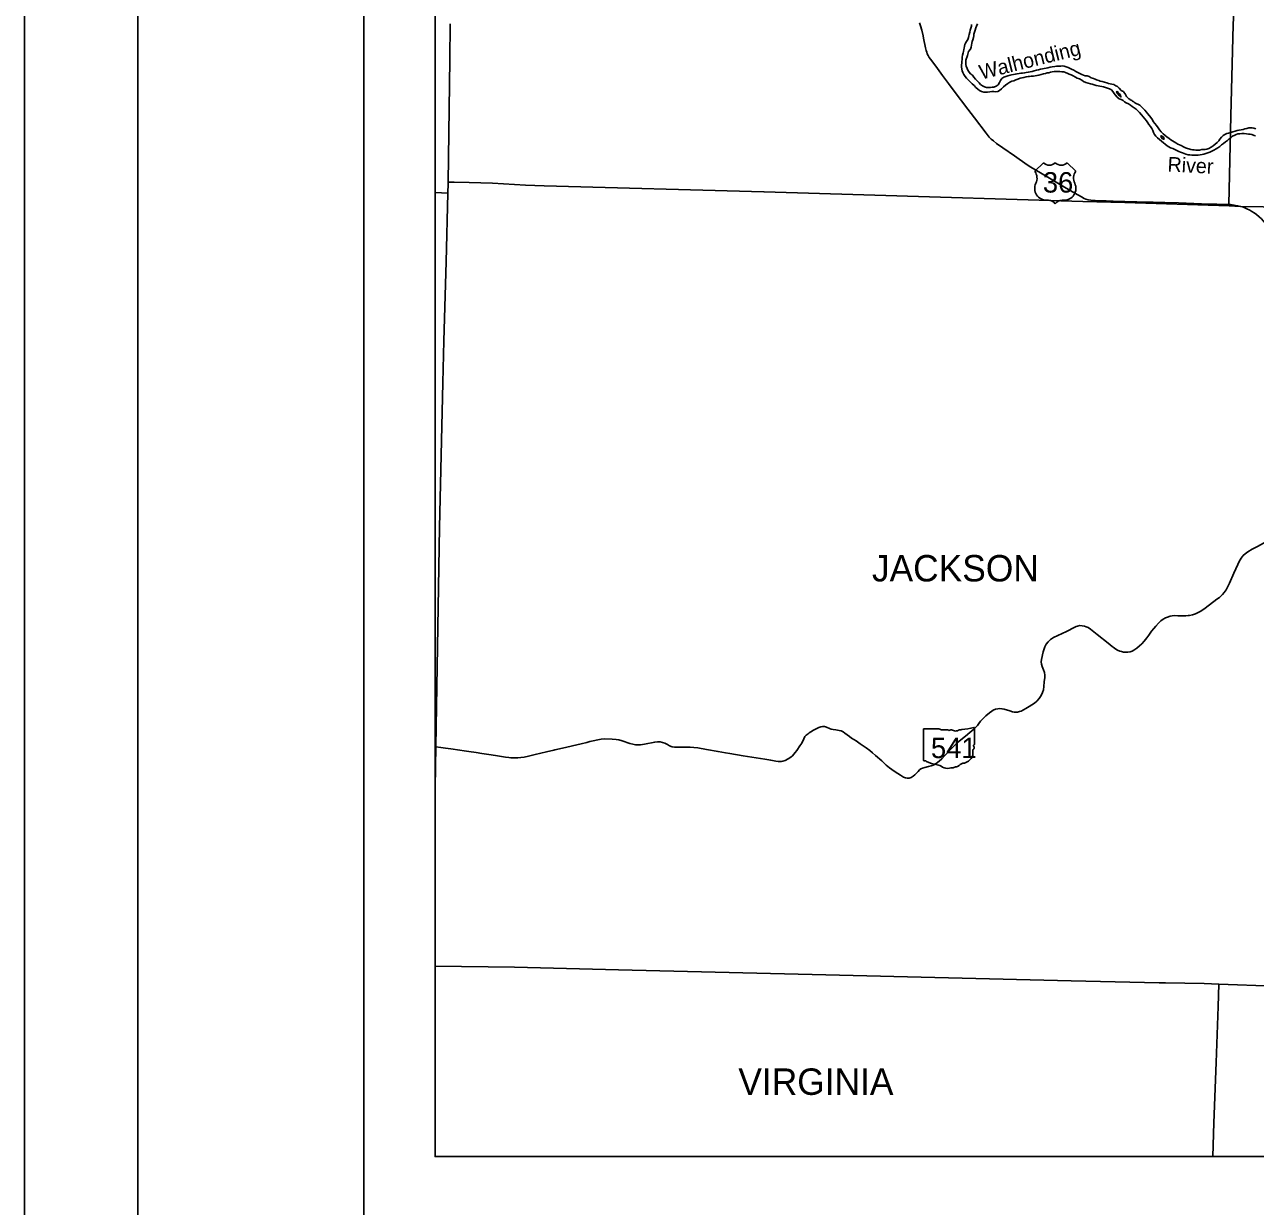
# Model space of a CAD drawing. Extents: x -6.3 to 34, y 0 to 22.
# Drawn here: x 0 to 5.44, y 9.17 to 14.39 of the extents above; entities that cross this region are included whole.
import ezdxf

# ---------------------------------------------------------------- set-up
doc = ezdxf.new("R2010")
doc.units = 0
for name, color, linetype in [('GM_X_Major_River', 7, 'Continuous'), ('GM_X_Major_River_Text', 7, 'Continuous'), ('GM_X_State_Route', 7, 'Continuous'), ('GM_X_State_Shield', 7, 'Continuous'), ('GM_X_Township', 7, 'Continuous'), ('GM_X_Township_Text', 7, 'Continuous'), ('GM_X_US_Location', 7, 'Continuous'), ('GM_X_US_Route', 7, 'Continuous'), ('GM_X_US_Shield', 7, 'Continuous'), ('SH_Border', 7, 'Continuous'), ('SH_Cut_Line', 7, 'Continuous'), ('SH_Text', 7, 'Continuous')]:
    doc.layers.add(name, color=color, linetype=linetype)

msp = doc.modelspace()

# ---------------------------------------------------------------- linework, layer by layer
at = {"layer": 'GM_X_Major_River'}
for p, q in [((4.1675, 14.2566), (4.1723, 14.273)), ((4.9522, 14.0147), (4.9299, 14.0357))]:
    msp.add_line(p, q, dxfattribs=at)
for points in [[(4.1861, 14.3926), (4.1851, 14.385), (4.1833, 14.3765), (4.1804, 14.3674), (4.1784, 14.3585), (4.1758, 14.3494), (4.1743, 14.3427), (4.1725, 14.3357), (4.1691, 14.3266), (4.1637, 14.3172), (4.1598, 14.3107), (4.157, 14.3042), (4.1554, 14.2977), (4.1534, 14.2883), (4.1518, 14.2818), (4.15, 14.2735), (4.1487, 14.267), (4.1467, 14.2574), (4.1452, 14.2488), (4.1441, 14.2387), (4.1431, 14.2299), (4.1424, 14.2218), (4.1416, 14.2145), (4.1416, 14.206), (4.1424, 14.1961), (4.1445, 14.1875), (4.1479, 14.1805), (4.1525, 14.1725), (4.1583, 14.1631), (4.1632, 14.1564), (4.1705, 14.1481), (4.1796, 14.1393), (4.1886, 14.1307), (4.1969, 14.1232), (4.2053, 14.1146), (4.2133, 14.1068), (4.2216, 14.1006), (4.2299, 14.097)], [(4.1723, 14.273), (4.1816, 14.2837), (4.1847, 14.292), (4.1852, 14.3009), (4.1868, 14.3097), (4.1888, 14.3178), (4.1911, 14.3258), (4.194, 14.3349), (4.196, 14.3432), (4.1968, 14.3497), (4.1988, 14.3588), (4.2019, 14.3682), (4.205, 14.3781), (4.2076, 14.3861), (4.2122, 14.3957)], [(4.8481, 14.1012), (4.8383, 14.1116), (4.8305, 14.1186), (4.8235, 14.1225), (4.8147, 14.1272), (4.8058, 14.1298), (4.7988, 14.1308), (4.7916, 14.1323), (4.7838, 14.1346), (4.7732, 14.1375), (4.7636, 14.1403), (4.7548, 14.1426), (4.748, 14.145), (4.7387, 14.1478), (4.7317, 14.1507), (4.7247, 14.1538), (4.7148, 14.1574), (4.7055, 14.1626), (4.6964, 14.1659), (4.6887, 14.1662), (4.6804, 14.169), (4.6736, 14.1716), (4.664, 14.1757), (4.6557, 14.1801), (4.6467, 14.1858), (4.6378, 14.1905), (4.6282, 14.1952), (4.6194, 14.1998), (4.6127, 14.2027), (4.6046, 14.2055), (4.5961, 14.2081), (4.5873, 14.2096), (4.5803, 14.2091), (4.5702, 14.2083), (4.5608, 14.208), (4.5541, 14.2078), (4.5427, 14.2062), (4.5331, 14.2038), (4.5238, 14.2017), (4.5165, 14.2001), (4.507, 14.1983), (4.5002, 14.197), (4.4914, 14.1952), (4.4818, 14.1926), (4.4725, 14.1905), (4.4629, 14.1881), (4.4539, 14.1847), (4.4453, 14.1834), (4.4365, 14.1818), (4.4277, 14.1805), (4.4205, 14.1789), (4.4119, 14.1784), (4.4034, 14.1771), (4.3958, 14.1758), (4.3873, 14.175), (4.3793, 14.1731), (4.3715, 14.1718), (4.3632, 14.1703), (4.356, 14.1689), (4.3469, 14.1661), (4.3378, 14.1637), (4.3288, 14.1606), (4.3197, 14.1535), (4.3145, 14.1455), (4.3094, 14.1366), (4.3037, 14.1268), (4.2941, 14.1197), (4.2845, 14.1166), (4.2768, 14.1153), (4.2698, 14.1142), (4.2604, 14.1139), (4.2519, 14.115), (4.2431, 14.1176), (4.2343, 14.122), (4.2257, 14.1282), (4.2192, 14.1344), (4.2119, 14.1419), (4.2041, 14.151), (4.1961, 14.1598), (4.1901, 14.1684), (4.1818, 14.1754), (4.1748, 14.1829), (4.1696, 14.1912), (4.167, 14.1987), (4.1626, 14.2081), (4.1605, 14.2166), (4.1602, 14.226), (4.1607, 14.2348), (4.1675, 14.2566)], [(4.2299, 14.097), (4.2398, 14.0939), (4.2563, 14.0945), (4.267, 14.0953), (4.276, 14.0963), (4.2841, 14.0961), (4.2931, 14.0956), (4.3019, 14.0971), (4.3102, 14.1016), (4.3182, 14.1078), (4.3275, 14.1172), (4.3366, 14.1247), (4.347, 14.1318), (4.3555, 14.138), (4.3643, 14.1417), (4.3734, 14.1435), (4.3819, 14.149), (4.391, 14.1508), (4.4005, 14.155), (4.4091, 14.1573), (4.4174, 14.1592), (4.4267, 14.1623), (4.4358, 14.1631), (4.4428, 14.1634), (4.4495, 14.1642), (4.4596, 14.1652), (4.4669, 14.1663), (4.4759, 14.1679), (4.484, 14.1689), (4.4935, 14.1715), (4.5034, 14.1741), (4.5122, 14.1768), (4.5202, 14.1786), (4.5275, 14.1799), (4.5355, 14.1815), (4.5422, 14.183), (4.5505, 14.1846), (4.5611, 14.1854), (4.5697, 14.1847), (4.5764, 14.1847), (4.585, 14.1836), (4.5933, 14.1834), (4.6018, 14.1808), (4.6109, 14.1764), (4.6177, 14.1738), (4.6262, 14.1705), (4.6358, 14.1656), (4.6449, 14.1601), (4.6534, 14.1562), (4.663, 14.1521), (4.6729, 14.1464), (4.6812, 14.1407), (4.6916, 14.136), (4.7022, 14.1332), (4.7123, 14.1306), (4.719, 14.1286), (4.7284, 14.1257), (4.7369, 14.1231), (4.7455, 14.1216), (4.7535, 14.12), (4.7623, 14.1185), (4.7691, 14.1167), (4.7782, 14.1141), (4.7872, 14.1113), (4.7955, 14.1079), (4.8043, 14.1043), (4.8108, 14.0965), (4.8158, 14.0885), (4.8212, 14.0815), (4.8293, 14.0724), (4.8384, 14.0641), (4.8474, 14.061), (4.856, 14.0568), (4.8627, 14.0517), (4.8697, 14.0465), (4.8791, 14.0415), (4.8882, 14.0364), (4.8967, 14.0307), (4.9055, 14.025), (4.9136, 14.0185), (4.9214, 14.0115), (4.9289, 14.0042), (4.9375, 13.9941), (4.945, 13.9853), (4.9523, 13.9762), (4.959, 13.9666), (4.9652, 13.958), (4.9702, 13.9513), (4.9777, 13.9414), (4.9824, 13.9326), (4.9868, 13.9238), (4.9905, 13.915), (4.9951, 13.9067), (5.0001, 13.8986), (5.0081, 13.8921), (5.0169, 13.8851), (5.0346, 13.8691), (5.0413, 13.8639), (5.0512, 13.8571), (5.0587, 13.8525), (5.066, 13.8483)], [(4.8293, 14.098), (4.827, 14.0941), (4.8386, 14.0789)], [(4.8386, 14.0789), (4.8396, 14.0771), (4.8462, 14.0721), (4.8446, 14.0817), (4.8342, 14.0915), (4.8293, 14.098)], [(4.9299, 14.0357), (4.921, 14.0402), (4.9171, 14.0425), (4.9113, 14.0456), (4.9085, 14.0469), (4.9056, 14.0484), (4.903, 14.0507), (4.8973, 14.0544), (4.8942, 14.0564), (4.8911, 14.0582), (4.8877, 14.0605), (4.8851, 14.0624), (4.8815, 14.0647), (4.8789, 14.0667), (4.8763, 14.0686), (4.8734, 14.0711), (4.8708, 14.074), (4.87, 14.0771), (4.8672, 14.0828), (4.8648, 14.0857), (4.863, 14.0885), (4.8596, 14.0939), (4.857, 14.0963), (4.8539, 14.0986), (4.8481, 14.1012)], [(5.4434, 13.9322), (5.4345, 13.935), (5.4262, 13.9366), (5.4182, 13.9363), (5.4115, 13.9355), (5.4029, 13.9339), (5.3939, 13.931), (5.3871, 13.9282), (5.3778, 13.9274), (5.3685, 13.9263), (5.3597, 13.9247), (5.3506, 13.9221), (5.3408, 13.919), (5.332, 13.9156), (5.3224, 13.9127), (5.3144, 13.9114), (5.3053, 13.907), (5.2986, 13.902), (5.2911, 13.8942), (5.2836, 13.8854), (5.2784, 13.8789), (5.2719, 13.8716), (5.2634, 13.8638), (5.2541, 13.8559), (5.245, 13.8502), (5.2344, 13.8447), (5.2259, 13.8419), (5.2191, 13.8406), (5.2103, 13.8398), (5.2036, 13.8397), (5.193, 13.8374), (5.1862, 13.8371), (5.1769, 13.8374), (5.1696, 13.8384), (5.1629, 13.8394), (5.1556, 13.8404), (5.1471, 13.8428), (5.1403, 13.8446), (5.1321, 13.8477), (5.1225, 13.8518), (5.1131, 13.8578), (5.1051, 13.8614), (5.0983, 13.8645), (5.0893, 13.8694), (5.0815, 13.8736), (5.0742, 13.8782), (5.0675, 13.8826), (5.0589, 13.8894), (5.049, 13.8961), (5.0426, 13.9028), (5.0335, 13.9101), (5.0247, 13.9179), (5.0169, 13.928), (5.0114, 13.9366), (5.0036, 13.9464), (4.9961, 13.9555), (4.9893, 13.9648), (4.9852, 13.9716), (4.9787, 13.9812), (4.9727, 13.9892), (4.9644, 13.9994), (4.9589, 14.0061), (4.9522, 14.0147)], [(5.0374, 13.8859), (5.0366, 13.8912), (5.0327, 13.8969), (5.0272, 13.9), (5.0249, 13.9014), (5.0226, 13.9002)], [(5.0226, 13.9002), (5.0244, 13.8953), (5.0281, 13.889), (5.034, 13.8862), (5.0374, 13.8859)], [(5.066, 13.8483), (5.0751, 13.8447), (5.0841, 13.8403), (5.0935, 13.8359), (5.1023, 13.8312), (5.1095, 13.8279), (5.1189, 13.825), (5.1261, 13.8225), (5.1337, 13.8196), (5.143, 13.8173), (5.1515, 13.8168), (5.1598, 13.816), (5.1694, 13.8153), (5.1777, 13.8148), (5.1876, 13.8158), (5.1961, 13.8169), (5.2049, 13.8179), (5.2129, 13.8203), (5.2215, 13.8226), (5.2308, 13.8255), (5.2391, 13.8289), (5.2476, 13.8333), (5.2572, 13.838), (5.2668, 13.843), (5.2751, 13.8472), (5.2828, 13.8531), (5.2911, 13.8607), (5.2991, 13.8675), (5.3079, 13.8737), (5.317, 13.8805), (5.3242, 13.8875), (5.333, 13.894), (5.34, 13.8992), (5.3496, 13.9037), (5.3563, 13.9071), (5.3633, 13.9092), (5.3719, 13.9102), (5.3815, 13.9108), (5.3905, 13.9118), (5.4019, 13.9092), (5.41, 13.9082), (5.4167, 13.9082), (5.4255, 13.9064), (5.4349, 13.9025), (5.4419, 13.9002)]]:
    msp.add_lwpolyline(points, dxfattribs=at)
at = {"layer": 'GM_X_State_Route'}
msp.add_line((2.3444, 11.1861), (2.391, 11.1972), dxfattribs=at)
for points in [[(5.3453, 11.967), (5.3629, 12.0059), (5.3691, 12.0191), (5.3782, 12.0344), (5.3873, 12.0457), (5.3954, 12.0531), (5.407, 12.0623), (5.4266, 12.0735), (5.4494, 12.0861), (5.5034, 12.1155), (5.5251, 12.1273)], [(2.391, 11.1972), (2.4225, 11.2048), (2.46, 11.2135), (2.4846, 11.2197), (2.4993, 11.2228), (2.5484, 11.2334), (2.5625, 11.2345), (2.5967, 11.2332), (2.6155, 11.2321), (2.6261, 11.2301), (2.6411, 11.2263), (2.676, 11.2152), (2.6892, 11.2116), (2.7008, 11.2091), (2.7097, 11.2083), (2.7219, 11.2091), (2.7395, 11.2122), (2.7859, 11.2205), (2.7979, 11.2216), (2.8092, 11.2215), (2.8203, 11.2197), (2.8295, 11.2167), (2.8412, 11.2099), (2.8505, 11.2041), (2.8619, 11.2002), (2.873, 11.1985), (2.8902, 11.1977), (2.9262, 11.1983), (2.9425, 11.1988), (2.9581, 11.1973), (2.9762, 11.195), (3.0149, 11.1881), (3.0654, 11.1792), (3.0818, 11.1766), (3.098, 11.1736), (3.1172, 11.1704), (3.1762, 11.1607), (3.2725, 11.145), (3.2984, 11.1406), (3.3203, 11.1371), (3.3305, 11.1356), (3.3392, 11.1351), (3.3463, 11.1356), (3.3517, 11.1369), (3.362, 11.1397), (3.3756, 11.1463), (3.3872, 11.1536), (3.3952, 11.1606), (3.4068, 11.1742), (3.4136, 11.1834), (3.4275, 11.2038), (3.435, 11.2166), (3.4439, 11.2359), (3.4489, 11.245), (3.4551, 11.2514), (3.463, 11.2578), (3.468, 11.2612), (3.4749, 11.266), (3.4874, 11.2735), (3.5108, 11.2846), (3.5197, 11.2878), (3.5277, 11.2897), (3.5361, 11.2894), (3.5442, 11.2869), (3.5581, 11.2808), (3.5661, 11.278), (3.5747, 11.276), (3.5859, 11.2744), (3.6007, 11.2724), (3.6103, 11.2699), (3.618, 11.266), (3.6264, 11.2608), (3.6365, 11.2526), (3.6465, 11.2448), (3.656, 11.2387), (3.6756, 11.2261), (3.694, 11.213), (3.7204, 11.1947), (3.7363, 11.1831), (3.7477, 11.1738), (3.7616, 11.1615), (3.7887, 11.1374), (3.8092, 11.119), (3.8226, 11.1076), (3.8331, 11.0996), (3.8442, 11.0918), (3.8601, 11.0816), (3.8722, 11.0739), (3.8854, 11.0664), (3.8945, 11.0623), (3.9014, 11.0609), (3.9102, 11.0611), (3.9187, 11.0641), (3.9277, 11.0695), (3.935, 11.0757), (3.9494, 11.0914), (3.9563, 11.098), (3.9624, 11.1023), (3.969, 11.1058), (3.9796, 11.1089), (3.9954, 11.1123), (4.0072, 11.1155), (4.017, 11.1192), (4.0295, 11.1262), (4.0427, 11.1363), (4.0543, 11.1474), (4.0674, 11.162), (4.0903, 11.1858), (4.1035, 11.1991), (4.1236, 11.2185), (4.1585, 11.2475), (4.1779, 11.2632), (4.1957, 11.2773), (4.2036, 11.2847), (4.212, 11.2943), (4.2178, 11.3023), (4.2261, 11.3135), (4.2371, 11.3258), (4.2493, 11.3371), (4.2655, 11.3507), (4.2757, 11.3579), (4.2821, 11.3615), (4.2919, 11.3657), (4.3028, 11.3684), (4.3105, 11.3693), (4.3203, 11.3684), (4.3306, 11.3663), (4.3549, 11.3586), (4.3675, 11.3552), (4.375, 11.3538), (4.3816, 11.3536), (4.3891, 11.3538), (4.3973, 11.3554), (4.4053, 11.3581), (4.4155, 11.3631), (4.4258, 11.3691), (4.4407, 11.3784), (4.4642, 11.3934), (4.4744, 11.4018), (4.4845, 11.4128), (4.4943, 11.4271), (4.5001, 11.4406), (4.5033, 11.4521), (4.5058, 11.467), (4.5075, 11.4876), (4.5095, 11.5056), (4.5095, 11.5163), (4.5079, 11.5286), (4.5038, 11.5407), (4.4983, 11.5552), (4.4949, 11.566), (4.494, 11.5757), (4.4954, 11.5856), (4.5028, 11.6202), (4.5065, 11.6329), (4.5104, 11.6426), (4.5161, 11.6534), (4.5241, 11.6641), (4.5348, 11.674), (4.5487, 11.6827), (4.568, 11.6922), (4.6056, 11.7102), (4.6421, 11.7289), (4.6479, 11.7312), (4.6547, 11.7337), (4.6649, 11.7355), (4.6748, 11.7353), (4.6848, 11.7338), (4.6933, 11.731), (4.7022, 11.7269), (4.7123, 11.72), (4.7417, 11.6964), (4.7895, 11.6582), (4.807, 11.6441), (4.8123, 11.6401), (4.8231, 11.6323), (4.8313, 11.6275), (4.8418, 11.6229), (4.8495, 11.6206), (4.8577, 11.619), (4.8672, 11.618), (4.8766, 11.6183), (4.8866, 11.6201), (4.8954, 11.6229), (4.9036, 11.6267), (4.9161, 11.6354), (4.9291, 11.6465), (4.9381, 11.6554), (4.9494, 11.6675), (4.9604, 11.6811), (4.9693, 11.6933), (4.9817, 11.7115), (4.9914, 11.7236), (5.0003, 11.7338), (5.0129, 11.7469), (5.0229, 11.7563), (5.0331, 11.7637), (5.0431, 11.7694), (5.0523, 11.7735), (5.0638, 11.777), (5.0726, 11.7786), (5.0833, 11.7798), (5.0981, 11.7794), (5.123, 11.7788), (5.1337, 11.7791), (5.1429, 11.7801), (5.1499, 11.7811), (5.1629, 11.7837), (5.1754, 11.7878), (5.188, 11.7934), (5.1996, 11.8001), (5.2183, 11.8128), (5.2707, 11.8521), (5.2815, 11.8606), (5.295, 11.873), (5.3024, 11.8817), (5.3114, 11.8943), (5.3194, 11.9082), (5.3263, 11.9227), (5.3453, 11.967)], [(1.8145, 11.2008), (1.8176, 11.2003), (1.8394, 11.1972), (1.8602, 11.1941), (1.8845, 11.1905), (1.9233, 11.185), (1.9433, 11.182), (1.9631, 11.1791), (1.9955, 11.1743), (2.0216, 11.1703), (2.0412, 11.1675), (2.062, 11.1646), (2.0907, 11.1602), (2.1262, 11.1548), (2.1398, 11.1529), (2.1492, 11.1518), (2.1639, 11.1508), (2.1799, 11.1508), (2.1938, 11.1523), (2.2088, 11.1545), (2.2274, 11.1588), (2.2576, 11.1659), (2.307, 11.1773), (2.339, 11.1849), (2.3444, 11.1861)]]:
    msp.add_lwpolyline(points, dxfattribs=at)
at = {"layer": 'GM_X_State_Shield'}
for p, q in [((3.9732, 11.2774), (3.9732, 11.1403)), ((4.0415, 11.2798), (3.9754, 11.2798)), ((4.199, 11.2114), (4.199, 11.2832)), ((4.199, 11.2115), (4.199, 11.2114))]:
    msp.add_line(p, q, dxfattribs=at)
for centre, major_axis, start_param, end_param in [((3.9758, 11.2777), (0.00262, 0), 1.712693, 3.28349), ((4.0573, 11.2957), (0.0254, 0), 4.042523, 4.731795), ((4.0657, 11.2028), (0.0911, 0), 1.404758, 1.657858), ((4.0864, 11.2784), (0.00732, 0), 3.836095, 5.185415), ((4.0971, 11.2626), (0.0152, 0), 0.950623, 2.079405), ((4.1168, 11.2843), (0.0183, 0), 4.081561, 5.145723), ((4.1491, 11.2379), (0.0482, 0), 1.699011, 2.107814), ((4.1186, 11.4668), (0.2395, 0), 4.814394, 5.042369), ((4.1965, 11.2835), (0.00251, 0), 6.141152, 7.989035), ((4.1985, 11.2062), (0.00389, 0), 1.883978, 3.671073), ((4.1964, 11.2112), (0.00269, 0), 5.05454, 6.418171), ((4.132, 11.1723), (0.0599, 0), 5.101752, 6.440018), ((4.2081, 11.1814), (0.017, 0), 2.387724, 3.262537), ((4.1737, 11.1971), (0.0234, 0), 5.934695, 6.695948), ((3.9758, 11.14), (0.00264, 0), 3.00124, 4.508301), ((3.9762, 11.154), (0.0201, 0), 4.665946, 4.897461), ((3.9803, 11.1324), (0.00726, 0), 0.519207, 1.627899), ((4.072, 11.2556), (0.173, 0), 4.195997, 4.488961), ((4.0204, 11.0787), (0.0541, 0), 0.823519, 1.323587), ((4.079, 11.1317), (0.0343, 0), 4.026481, 4.996735), ((4.0988, 11.0843), (0.0282, 0), 1.495662, 1.94098), ((4.1013, 11.1214), (0.0183, 0), 4.691044, 5.507374), ((4.1179, 11.1081), (0.00515, 0), 1.147584, 2.315152), ((4.1157, 11.127), (0.0194, 0), 4.937069, 5.64225), ((4.1573, 11.1018), (0.0328, 0), 1.647645, 2.488434)]:
    msp.add_ellipse(centre, major_axis=major_axis, ratio=0.8, start_param=start_param, end_param=end_param, dxfattribs=at)
at = {"layer": 'GM_X_Township'}
msp.add_line((1.8714, 13.6475), (1.8145, 13.6505), dxfattribs=at)
for points in [[(5.3462, 14.4809), (5.3422, 14.3911), (5.3327, 13.9887), (5.3239, 13.5973), (5.3241, 13.5916), (4.8634, 13.606), (4.6774, 13.6107), (3.7105, 13.6402), (3.2686, 13.6537), (3.2682, 13.6537), (2.296, 13.6801), (2.2145, 13.6823), (2.0679, 13.6908), (1.9649, 13.6941), (1.8995, 13.6959), (1.8729, 13.6966), (1.879, 14.2362), (1.8808, 14.3961)], [(1.8729, 13.6966), (1.8727, 13.6895), (1.8714, 13.6475), (1.8628, 13.3431), (1.8531, 12.9951), (1.849, 12.8091), (1.8338, 12.1688), (1.8174, 11.2007), (1.8145, 11.0198)], [(5.5251, 13.5846), (5.5251, 13.5846), (5.5212, 13.5848), (5.475, 13.587), (5.3756, 13.5889), (5.3241, 13.5916)], [(1.8145, 10.2308), (2.1653, 10.2253), (2.4525, 10.2187), (2.6257, 10.2147), (3.5425, 10.1923), (4.626, 10.1654), (5.0158, 10.1572), (5.044, 10.1567), (5.215, 10.1532), (5.2784, 10.1511), (5.5251, 10.142)], [(5.2784, 10.1511), (5.2784, 10.1511), (5.2763, 10.0521), (5.2671, 9.8039), (5.2571, 9.5375), (5.2521, 9.3884)]]:
    msp.add_lwpolyline(points, dxfattribs=at)
at = {"layer": 'GM_X_US_Route'}
for points in [[(3.956, 14.4005), (3.9604, 14.3864), (3.9656, 14.3675), (3.9717, 14.343)], [(3.9717, 14.343), (3.9741, 14.3331), (3.9829, 14.2898), (3.9851, 14.2786), (3.9878, 14.2707), (3.9901, 14.2639), (3.9943, 14.2552), (3.9993, 14.2475), (4.0049, 14.2401), (4.0281, 14.2086), (4.0577, 14.1679), (4.0844, 14.1317), (4.1093, 14.0988), (4.1698, 14.019), (4.1996, 13.9804), (4.2509, 13.9126), (4.2645, 13.8956), (4.2731, 13.8865), (4.2824, 13.8783), (4.297, 13.8671), (4.3242, 13.8481), (4.3756, 13.8119), (4.4322, 13.7723), (4.4485, 13.7616), (4.5158, 13.7221), (4.5971, 13.6745), (4.6425, 13.6478), (4.6713, 13.6307), (4.6841, 13.6239)], [(4.6841, 13.6239), (4.6911, 13.6209), (4.7013, 13.6177), (4.713, 13.6158), (4.7329, 13.6149), (4.781, 13.6134), (4.8423, 13.611), (4.8636, 13.6106)], [(4.8636, 13.6106), (4.9165, 13.6097), (4.9882, 13.6077), (5.0405, 13.6061), (5.1009, 13.6043), (5.2029, 13.6009), (5.2699, 13.599), (5.3014, 13.5978)], [(5.3014, 13.5978), (5.324, 13.5969), (5.3307, 13.5965), (5.3457, 13.5948), (5.3623, 13.592), (5.3758, 13.5885)], [(5.3758, 13.5885), (5.388, 13.5847), (5.403, 13.5784), (5.4165, 13.5719), (5.4252, 13.567), (5.4355, 13.5602), (5.4463, 13.5526), (5.4573, 13.5433), (5.4674, 13.5336), (5.4758, 13.5247), (5.4859, 13.5131), (5.5011, 13.4954), (5.5251, 13.4677)]]:
    msp.add_lwpolyline(points, dxfattribs=at)
at = {"layer": 'GM_X_US_Shield'}
for p, q in [((4.5036, 13.7816), (4.4659, 13.744)), ((4.6466, 13.744), (4.609, 13.7816)), ((4.5186, 13.616), (4.5261, 13.616)), ((4.5864, 13.616), (4.5939, 13.616))]:
    msp.add_line(p, q, dxfattribs=at)
for centre, radius, start, end in [((4.5299, 13.8085), 0.0376, 225.573, 314.427), ((4.5826, 13.8085), 0.0376, 225.573, 314.427), ((4.4227, 13.7137), 0.0527, 334.5471, 35.0009), ((4.6898, 13.7137), 0.0527, 144.9991, 205.4529), ((4.518, 13.6687), 0.0527, 154.8319, 270.6383), ((4.5945, 13.6687), 0.0527, 269.3617, 25.1681), ((4.5261, 13.5783), 0.0376, 36.8699, 90), ((4.5864, 13.5783), 0.0376, 90, 143.1301)]:
    msp.add_arc(centre, radius, start, end, dxfattribs=at)
at = {"layer": 'SH_Border'}
for points in [[(0.5, 21.5), (1.5, 21.5), (1.5, 0.5), (0.5, 0.5)], [(1.5, 21.5), (33.5, 21.5), (33.5, 0.5), (1.5, 0.5)]]:
    msp.add_lwpolyline(points, close=True, dxfattribs=at)
at = {"layer": 'SH_Cut_Line'}
msp.add_lwpolyline([(0, 0), (34, 0), (34, 22), (0, 22)], close=True, dxfattribs=at)
at = {"layer": 'SH_Text'}
msp.add_lwpolyline([(1.8145, 20.7482), (12.189, 20.7482), (12.189, 9.3884), (1.8145, 9.3884)], close=True, dxfattribs=at)

# ---------------------------------------------------------------- texts
at = {"layer": 'GM_X_Major_River_Text'}
for s, rotation, p in [('Walhonding', 13.9879, (4.2291, 14.1491)), ('River', 356.9856, (5.0511, 13.7434))]:
    msp.add_text(s, height=0.0649, rotation=rotation, dxfattribs=at).set_placement(p)
at = {"layer": 'GM_X_State_Shield'}
msp.add_text('541', height=0.09035, dxfattribs=at).set_placement((4.0065, 11.15))
at = {"layer": 'GM_X_Township_Text'}
for s, p in [('JACKSON', (3.7455, 11.9309)), ('VIRGINIA', (3.155, 9.6614))]:
    msp.add_text(s, height=0.11682, rotation=0, dxfattribs=at).set_placement(p)
at = {"layer": 'GM_X_US_Location'}
msp.add_text('36', height=0.00013, rotation=0, dxfattribs=at).set_placement((4.5459, 13.679))
for s in ['0', '/']:
    msp.add_text(s, height=0.00013, dxfattribs=at).set_placement((4.5727, 13.7059))
at = {"layer": 'GM_X_US_Shield'}
msp.add_text('36', height=0.09035, dxfattribs=at).set_placement((4.5012, 13.6499))

doc.saveas('drawing.dxf')
